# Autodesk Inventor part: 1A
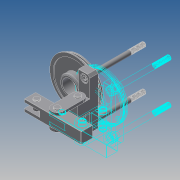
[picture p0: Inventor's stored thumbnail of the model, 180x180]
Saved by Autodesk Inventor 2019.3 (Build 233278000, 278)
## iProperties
Created: 2013-07
Part Number: 1A
Material: Ogólny
Document SubType Name: Modeling
Designer: Admin
Density: 1 g/cm^3
Appearance: Domyślna
Author: Admin
Revision Number: ÈÎºÎ
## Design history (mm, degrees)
feature "M12-120_GB_FASTENER_SCREWS_HSHCS M10X100-N-1-solid1"
feature "M12-120_GB_FASTENER_SCREWS_HSHCS M10X100-N-2-solid1"
feature "circlips for holes--type a gb_GB_CONNECTING_PIECE_RING_RRH 1"
feature "CALC-100-03-1-solid1"
feature "CALC-100-04Ö§³Å¿é-1-solid1"
feature "CALC100-Ç°¸Ç.bak-1-solid1"
node "Bryła1"
node "Bryła2"
node "Bryła3"
node "Bryła5"
node "Bryła10"
node "Bryła11"
